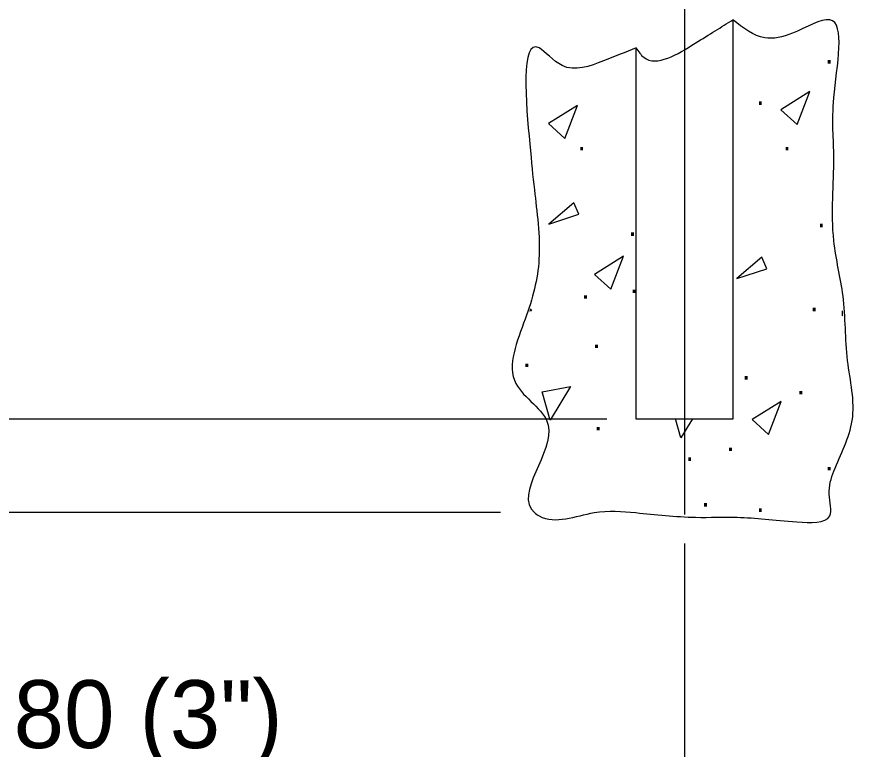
# Model space of a CAD drawing. Extents: x -4 to 901, y -468 to 720.
# Drawn here: x 89.67 to 131.24, y -370.16 to -333.88 of the extents above; entities that cross this region are included whole.
import ezdxf

# ---------------------------------------------------------------- set-up
doc = ezdxf.new("R2010")
doc.units = 0
doc.layers.add('2', color=7, linetype='Continuous')
doc.layers.add('3', color=7, linetype='Continuous')

msp = doc.modelspace()

# ---------------------------------------------------------------- linework, layer by layer
at = {"layer": '2'}
for p, q in [((122.77575, -329.945625), (122.77575, -358.535625)), ((118.93575, -353.807625), (65.93175, -353.807625)), ((113.65575, -358.443625), (81.08575, -358.443625)), ((122.77575, -359.975625), (122.77575, -379.486375))]:
    msp.add_line(p, q, dxfattribs=at)
for points in [[(125.17575, -334.025625), (125.17575, -353.807625), (120.37575, -353.807625), (120.37575, -335.417625)], [(115.19575, -348.443625), (115.09975, -348.465625)], [(115.12775, -348.337625), (115.19575, -348.443625)], [(130.61575, -348.683625), (130.60975, -348.447625)], [(130.62575, -348.681625), (130.61575, -348.683625)], [(115.72375, -352.463625), (117.12775, -352.187625)], [(116.11975, -353.855625), (115.72375, -352.463625)], [(117.12775, -352.187625), (116.11975, -353.855625)], [(122.59975, -354.743625), (122.32975, -353.797625)], [(123.17375, -353.793625), (122.59975, -354.743625)]]:
    msp.add_lwpolyline(points, dxfattribs=at)
for points in [[(128.99175, -337.577625), (127.55175, -338.477625), (128.36775, -339.209625)], [(117.47575, -338.267625), (116.03575, -339.167625), (116.85175, -339.899625)], [(117.53775, -343.661625), (117.28575, -343.085625), (116.04975, -344.153625)], [(119.75575, -345.743625), (118.31575, -346.643625), (119.13175, -347.375625)], [(126.85975, -346.355625), (126.60775, -345.779625), (125.37175, -346.847625)], [(127.56775, -352.931625), (126.12775, -353.831625), (126.94375, -354.563625)]]:
    msp.add_lwpolyline(points, close=True, dxfattribs=at)
for points in [[(120.37575, -335.417625), (118.76175, -336.061625), (116.70575, -336.289625), (115.57575, -335.417625), (115.10775, -340.173625), (115.33575, -342.455625), (115.56375, -345.881625), (114.87975, -348.851625), (114.42175, -352.049625), (116.02175, -354.103625), (115.33575, -358.443625), (115.57575, -358.607625), (118.30575, -358.443625), (120.35975, -358.443625), (123.32975, -358.671625), (125.38575, -358.671625), (128.35375, -358.899625), (129.97575, -358.607625), (129.95175, -357.529625), (130.18175, -356.387625), (131.09375, -353.875625), (130.86575, -350.907625), (130.63775, -347.709625), (130.18175, -344.969625), (130.18175, -340.857625), (130.18175, -337.889625), (129.97575, -334.025625), (128.12575, -334.691625), (126.75575, -334.919625), (125.17575, -334.025625)], [(120.37575, -335.417625), (120.75775, -335.883625), (123.31175, -335.185625), (125.17575, -334.025625)]]:
    msp.add_spline(points, degree=3, dxfattribs=at)

# ---------------------------------------------------------------- texts
for p in [(129.73975, -336.191625), (126.33175, -338.243625), (117.47575, -340.499625), (127.65175, -340.499625), (129.35575, -344.303625), (119.99575, -344.735625), (120.07975, -347.567625), (117.66775, -347.843625), (128.99575, -348.467625), (118.20775, -350.291625), (114.75175, -351.227625), (125.62375, -351.851625), (128.33575, -352.583625), (118.29175, -354.371625), (124.85575, -355.391625), (122.82775, -355.883625), (129.73975, -356.351625), (123.60775, -358.139625), (126.33175, -358.403625)]:
    msp.add_text('.', height=1.116, dxfattribs=at).set_placement(p)
at = {"layer": '3'}
msp.add_text('80 (3")', height=3.36, dxfattribs=at).set_placement((89.51975, -370.105625))

doc.saveas('drawing.dxf')
